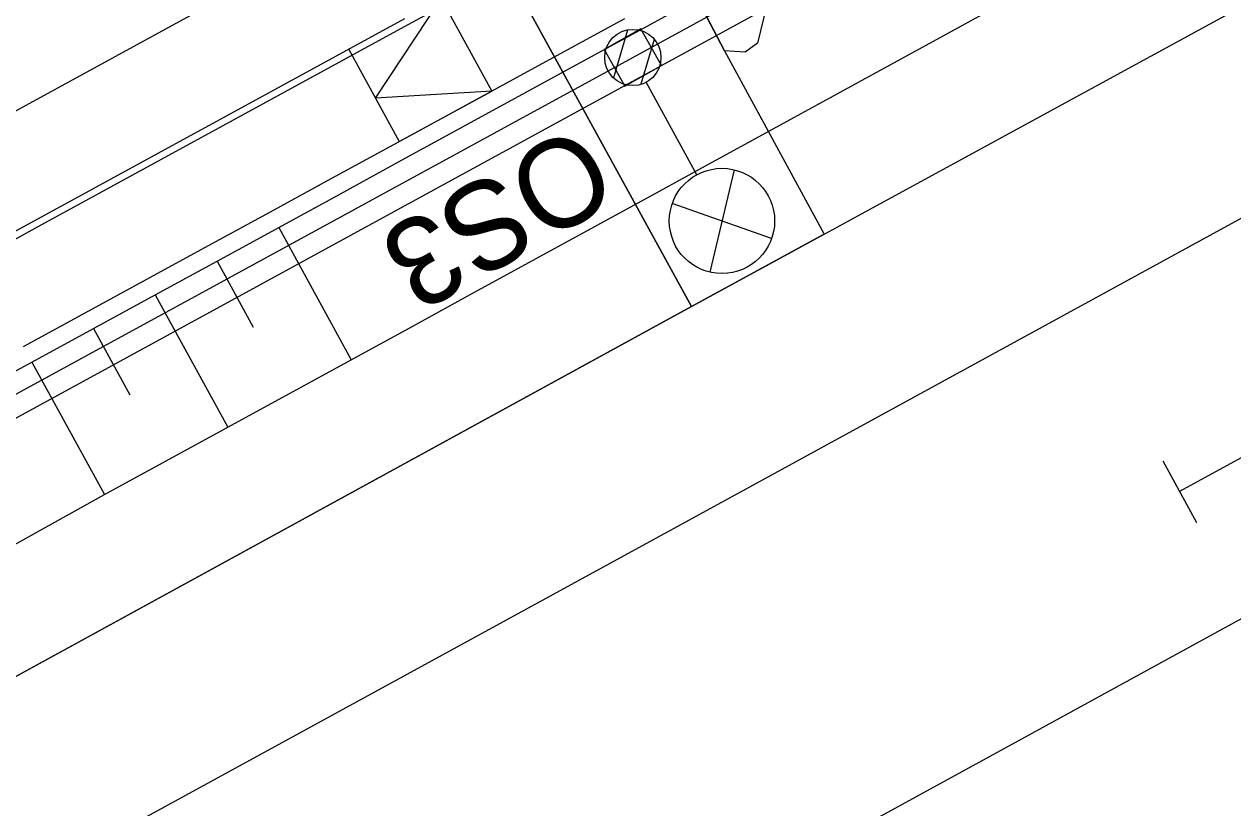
# Model space of a CAD drawing. Extents: x -783978 to -783565, y -1064821 to -1064596.
# Drawn here: x -783793.32 to -783776.13, y -1064707.57 to -1064696.42 of the extents above; entities that cross this region are included whole.
import ezdxf

# ---------------------------------------------------------------- set-up
doc = ezdxf.new("R2010")
doc.units = 0
for name, color, linetype in [('PS 01_01_10', 7, 'Continuous'), ('PS 01_02_501', 7, 'Continuous'), ('PS 01_02_502', 7, 'Continuous'), ('SO 01_10_01', 7, 'Continuous'), ('SO 01_50_01', 7, 'Continuous'), ('SO 01_79_02', 7, 'Continuous'), ('SO 01_86_02', 7, 'Continuous'), ('SO 01_86_03', 7, 'Continuous')]:
    doc.layers.add(name, color=color, linetype=linetype)

msp = doc.modelspace()

# ---------------------------------------------------------------- linework, layer by layer
at = {"layer": 'PS 01_01_10'}
msp.add_lwpolyline([(-783718.942, -1064658.936), (-783725.964, -1064662.689), (-783732.354, -1064665.912), (-783735.21, -1064660.697), (-783789.362, -1064690.348), (-783783.825, -1064700.441), (-783871.436, -1064748.425), (-783875.857, -1064749.835)], dxfattribs=at)
at = {"layer": 'PS 01_02_501'}
for points in [[(-783952.311, -1064789.972), (-783925.027, -1064771.233), (-783922.857, -1064767.935), (-783921.132, -1064767.225), (-783922.344, -1064769.056), (-783920.816, -1064771.043), (-783917.67, -1064770.417), (-783911.05, -1064766.471), (-783887.429, -1064753.525), (-783871.436, -1064748.425), (-783783.828, -1064700.439), (-783789.362, -1064690.348), (-783735.226, -1064660.707), (-783727.19, -1064659.072), (-783724.297, -1064658.484), (-783715.521, -1064653.988), (-783697.391, -1064644.148), (-783676.268, -1064633.506), (-783655.138, -1064621.894)], [(-783783.828, -1064700.439), (-783759.588, -1064687.223), (-783745.5, -1064712.799)]]:
    msp.add_lwpolyline(points, dxfattribs=at)
at = {"layer": 'PS 01_02_502'}
for points in [[(-783952.311, -1064789.972), (-783925.027, -1064771.233), (-783922.857, -1064767.935), (-783921.132, -1064767.225), (-783922.344, -1064769.056), (-783920.816, -1064771.043), (-783917.67, -1064770.417), (-783911.05, -1064766.471), (-783887.429, -1064753.525), (-783871.436, -1064748.425), (-783783.828, -1064700.439), (-783789.362, -1064690.348), (-783735.226, -1064660.707), (-783727.19, -1064659.072), (-783724.297, -1064658.484), (-783715.521, -1064653.988), (-783697.391, -1064644.148), (-783676.268, -1064633.506), (-783655.138, -1064621.894)], [(-783783.828, -1064700.439), (-783759.588, -1064687.223), (-783745.5, -1064712.799)]]:
    msp.add_lwpolyline(points, dxfattribs=at)
at = {"layer": 'SO 01_10_01'}
for p, q in [((-783749.277, -1064684.559), (-783793.141, -1064708.557)), ((-783790.742, -1064712.943), (-783746.877, -1064688.946)), ((-783777.123, -1064702.634), (-783776.642, -1064703.511))]:
    msp.add_line(p, q, dxfattribs=at)
msp.add_lwpolyline([(-783774.961, -1064706.581), (-783773.207, -1064705.62), (-783775.128, -1064702.112), (-783776.883, -1064703.072)], dxfattribs=at)
at = {"layer": 'SO 01_50_01'}
for p, q in [((-783867.163, -1064737.91), (-783786.213, -1064693.707)), ((-783787.855, -1064696.427), (-783786.978, -1064695.948)), ((-783788.781, -1064696.818), (-783787.903, -1064696.339)), ((-783788.78, -1064696.819), (-783787.903, -1064696.34)), ((-783788.733, -1064696.906), (-783787.855, -1064696.427)), ((-783785.429, -1064696.697), (-783784.775, -1064696.34)), ((-783785.309, -1064696.917), (-783784.655, -1064696.56)), ((-783785.309, -1064696.917), (-783784.655, -1064696.56)), ((-783785.309, -1064696.917), (-783784.655, -1064696.56)), ((-783786.307, -1064697.176), (-783785.429, -1064696.697)), ((-783789.659, -1064697.298), (-783788.781, -1064696.818)), ((-783789.658, -1064697.299), (-783788.78, -1064696.819)), ((-783789.611, -1064697.385), (-783788.733, -1064696.906)), ((-783786.187, -1064697.396), (-783785.309, -1064696.917)), ((-783786.187, -1064697.396), (-783785.309, -1064696.917)), ((-783786.187, -1064697.396), (-783785.309, -1064696.917)), ((-783790.536, -1064697.777), (-783789.659, -1064697.298)), ((-783790.536, -1064697.778), (-783789.658, -1064697.299)), ((-783787.184, -1064697.656), (-783786.307, -1064697.176)), ((-783790.488, -1064697.865), (-783789.611, -1064697.385)), ((-783787.065, -1064697.875), (-783786.187, -1064697.396)), ((-783787.065, -1064697.875), (-783786.187, -1064697.396)), ((-783787.065, -1064697.875), (-783786.187, -1064697.396)), ((-783788.062, -1064698.135), (-783787.184, -1064697.656)), ((-783791.414, -1064698.256), (-783790.536, -1064697.777)), ((-783791.413, -1064698.257), (-783790.536, -1064697.778)), ((-783791.366, -1064698.344), (-783790.488, -1064697.865)), ((-783787.942, -1064698.354), (-783787.065, -1064697.875)), ((-783787.942, -1064698.354), (-783787.065, -1064697.875)), ((-783787.942, -1064698.354), (-783787.065, -1064697.875)), ((-783788.94, -1064698.614), (-783788.062, -1064698.135)), ((-783792.292, -1064698.735), (-783791.414, -1064698.256)), ((-783792.291, -1064698.736), (-783791.413, -1064698.257)), ((-783792.244, -1064698.823), (-783791.366, -1064698.344)), ((-783788.82, -1064698.834), (-783787.942, -1064698.354)), ((-783788.82, -1064698.834), (-783787.942, -1064698.354)), ((-783788.82, -1064698.834), (-783787.942, -1064698.354)), ((-783784.282, -1064698.797), (-783783.629, -1064698.439)), ((-783789.817, -1064699.093), (-783788.94, -1064698.614)), ((-783793.169, -1064699.215), (-783792.292, -1064698.735)), ((-783793.169, -1064699.216), (-783792.291, -1064698.736)), ((-783793.121, -1064699.302), (-783792.244, -1064698.823)), ((-783789.698, -1064699.313), (-783788.82, -1064698.834)), ((-783789.698, -1064699.313), (-783788.82, -1064698.834)), ((-783789.698, -1064699.313), (-783788.82, -1064698.834)), ((-783785.16, -1064699.277), (-783784.282, -1064698.797)), ((-783790.695, -1064699.573), (-783789.817, -1064699.093)), ((-783794.047, -1064699.694), (-783793.169, -1064699.215)), ((-783794.046, -1064699.695), (-783793.169, -1064699.216)), ((-783793.999, -1064699.782), (-783793.121, -1064699.302)), ((-783790.575, -1064699.792), (-783789.698, -1064699.313)), ((-783790.575, -1064699.792), (-783789.698, -1064699.313)), ((-783790.575, -1064699.792), (-783789.698, -1064699.313)), ((-783789.698, -1064699.313), (-783788.669, -1064701.197)), ((-783786.037, -1064699.757), (-783785.16, -1064699.277)), ((-783791.573, -1064700.052), (-783790.695, -1064699.573)), ((-783791.453, -1064700.271), (-783790.575, -1064699.792)), ((-783791.453, -1064700.271), (-783790.575, -1064699.792)), ((-783791.453, -1064700.271), (-783790.575, -1064699.792)), ((-783790.575, -1064699.792), (-783790.061, -1064700.734)), ((-783786.914, -1064700.237), (-783786.037, -1064699.757)), ((-783792.45, -1064700.531), (-783791.573, -1064700.052)), ((-783787.792, -1064700.717), (-783786.914, -1064700.237)), ((-783792.331, -1064700.751), (-783791.453, -1064700.271)), ((-783792.331, -1064700.751), (-783791.453, -1064700.271)), ((-783792.331, -1064700.751), (-783791.453, -1064700.271)), ((-783791.453, -1064700.271), (-783790.424, -1064702.156)), ((-783793.328, -1064701.01), (-783792.45, -1064700.531)), ((-783793.208, -1064701.23), (-783792.331, -1064700.751)), ((-783793.208, -1064701.23), (-783792.331, -1064700.751)), ((-783793.208, -1064701.23), (-783792.331, -1064700.751)), ((-783792.331, -1064700.751), (-783791.816, -1064701.694)), ((-783788.669, -1064701.197), (-783787.792, -1064700.717)), ((-783794.086, -1064701.709), (-783793.208, -1064701.23)), ((-783794.086, -1064701.709), (-783793.208, -1064701.23)), ((-783794.086, -1064701.709), (-783793.208, -1064701.23)), ((-783793.208, -1064701.23), (-783792.178, -1064703.116)), ((-783789.546, -1064701.677), (-783788.669, -1064701.197)), ((-783790.424, -1064702.156), (-783789.546, -1064701.677)), ((-783791.301, -1064702.636), (-783790.424, -1064702.156)), ((-783792.178, -1064703.116), (-783791.301, -1064702.636)), ((-783793.053, -1064703.601), (-783792.178, -1064703.116)), ((-783793.926, -1064704.089), (-783793.053, -1064703.601))]:
    msp.add_line(p, q, dxfattribs=at)
for points in [[(-783783.629, -1064698.439), (-783735.703, -1064672.219)], [(-783784.655, -1064696.56), (-783745.113, -1064674.926)], [(-783788.704, -1064696.775), (-783787.985, -1064698.093), (-783786.668, -1064697.374), (-783788.321, -1064697.477), (-783787.387, -1064696.057), (-783786.668, -1064697.374)]]:
    msp.add_lwpolyline(points, dxfattribs=at)
at = {"layer": 'SO 01_79_02'}
msp.add_lwpolyline([(-783745.082, -1064674.977), (-783746.507, -1064675.757), (-783748.147, -1064676.664), (-783749.691, -1064678.136), (-783784.257, -1064697.013), (-783798.19, -1064704.62), (-783800.06, -1064705.37), (-783802.52, -1064706.72), (-783803.71, -1064707.63), (-783853.11, -1064734.61), (-783855.1, -1064735.3), (-783857.05, -1064736.37), (-783858.65, -1064737.64), (-783871.68, -1064744.75), (-783877.056, -1064744.607), (-783887.429, -1064744.062), (-783898.089, -1064743.49), (-783899.421, -1064743.418)], dxfattribs=at)
at = {"layer": 'SO 01_86_02'}
for p, q in [((-783784.735, -1064696.507), (-783784.935, -1064697.186)), ((-783784.358, -1064696.64), (-783784.545, -1064697.276)), ((-783783.752, -1064698.564), (-783784.47, -1064697.247)), ((-783783.22, -1064698.493), (-783783.567, -1064699.95)), ((-783782.687, -1064699.47), (-783784.099, -1064698.973))]:
    msp.add_line(p, q, dxfattribs=at)
msp.add_lwpolyline([(-783878.186, -1064744.275), (-783875.129, -1064744.345), (-783874.695, -1064744.328), (-783873.251, -1064744.157), (-783872.314, -1064743.982), (-783871.219, -1064743.702), (-783870.515, -1064743.486), (-783869.798, -1064743.212), (-783869.177, -1064742.975), (-783868.711, -1064742.765), (-783868.395, -1064742.607), (-783868.078, -1064742.449), (-783860.975, -1064738.569), (-783850.672, -1064732.611), (-783846.246, -1064730.189), (-783839.947, -1064727.086), (-783822.426, -1064717.427), (-783813.356, -1064712.518), (-783804.285, -1064707.61), (-783794.474, -1064702.252), (-783784.661, -1064696.896), (-783775.734, -1064692.013), (-783766.806, -1064687.131), (-783750.626, -1064678.282)], dxfattribs=at)
msp.add_lwpolyline([(-783784.775, -1064697.305), (-783784.252, -1064697.01), (-783784.548, -1064696.487), (-783785.07, -1064696.783)], close=True, dxfattribs=at)
for centre, radius in [((-783784.661, -1064696.896), 0.4), ((-783783.393, -1064699.222), 0.749)]:
    msp.add_circle(centre, radius, dxfattribs=at)
at = {"layer": 'SO 01_86_03'}
msp.add_line((-783783.359, -1064696.803), (-783786.817, -1064690.18), dxfattribs=at)
for points in [[(-783722.521, -1064661.793), (-783724.821, -1064663.049), (-783735.21, -1064660.697), (-783787.333, -1064689.237), (-783786.817, -1064690.18), (-783783.359, -1064696.803), (-783781.939, -1064699.409), (-783783.828, -1064700.439), (-783871.436, -1064748.425), (-783875.857, -1064749.835), (-783877.538, -1064747.393), (-783875.857, -1064749.835), (-783887.429, -1064753.525), (-783911.05, -1064766.471), (-783917.67, -1064770.417), (-783920.816, -1064771.043), (-783922.344, -1064769.056), (-783922.498, -1064767.051)], [(-783747.03, -1064676.621), (-783747.624, -1064677.108), (-783750.73, -1064678.782), (-783751.666, -1064678.852), (-783782.681, -1064695.831), (-783782.888, -1064696.692), (-783783.062, -1064696.82), (-783783.359, -1064696.803), (-783786.817, -1064690.18), (-783787.333, -1064689.237), (-783735.21, -1064660.697), (-783724.821, -1064663.049), (-783722.521, -1064661.793)]]:
    msp.add_lwpolyline(points, dxfattribs=at)

# ---------------------------------------------------------------- texts
at = {"layer": 'SO 01_86_02'}
msp.add_text('OS3', height=1.25, rotation=209.446, dxfattribs=at).set_placement((-783785.424, -1064697.817))

doc.saveas('drawing.dxf')
